// Mitsubishi GX Works2 project: 39.1加到100（循环指令）   PLC: FX3U/FX3UC

PROGRAM MAIN
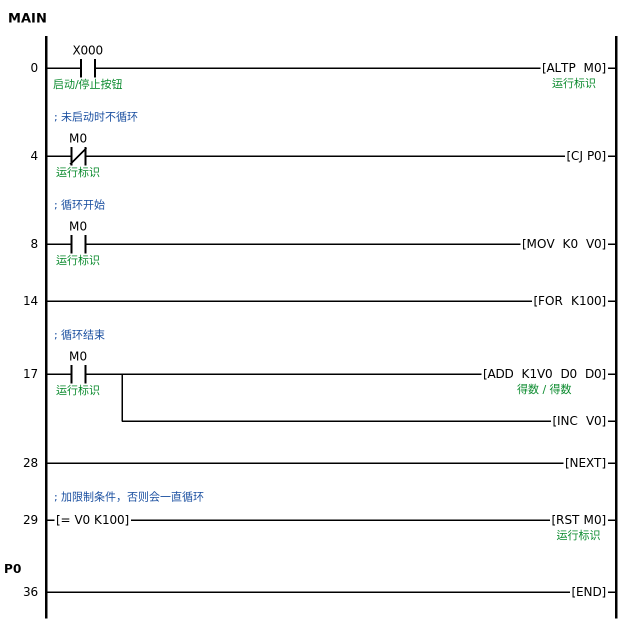
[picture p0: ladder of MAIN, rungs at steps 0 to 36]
0     LD      X000  ; 启动/停止按钮
      ALTP    M0  ; 运行标识
; 未启动时不循环
4     LDI     M0  ; 运行标识
      CJ      P0
8     LD      M0  ; 运行标识
      MOV     K0 V0
        [note] 把v0的值清空
; 循环开始
14    FOR     K100
        [note] 每隔运行周期循环100次
17    LD      M0  ; 运行标识
      ADD     K1V0 D0 D0  ; 得数
        [note] 1开始加V0
      INC     V0
        [note] V0自加一
; 循环结束
28    NEXT
; 加限制条件，否则会一直循环
29    LD=     V0 K100
      RST     M0  ; 运行标识
      P0
36    END
END_PROGRAM
